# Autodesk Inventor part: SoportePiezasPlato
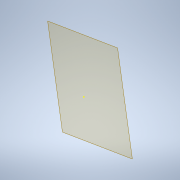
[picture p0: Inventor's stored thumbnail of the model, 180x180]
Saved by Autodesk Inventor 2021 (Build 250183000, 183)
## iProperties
Created: 2021-03
Part Number: SoportePiezasPlato
Material: Genérico
Document SubType Name: Modeling
Designer: ATOUZA
Density: 1 g/cm^3
Appearance: Valor por defecto
Author: ATOUZA
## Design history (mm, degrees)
node "Plano de trabajo1"
sketch "Boceto1"
  geometry: 1 further point
  constraints: 1 other
